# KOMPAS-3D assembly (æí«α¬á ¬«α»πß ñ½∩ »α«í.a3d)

Referenced files in D:\МОДЕЛЬ ТАНКА Т90\ПОДСБОРКИ\КОРПУС\: Сборка дно с пластиком.a3d, Сборка борт левый с пластиком.a3d, Сборка борт правый с пластиком.a3d, Сборка корпус лоб.a3d, Сборка корпус верх.a3d, Сборка корма.a3d, Сборка корма верх.a3d, Сборка крышка моторного.a3d, Сборка полка надгусеничная левая.a3d, Сборка полка надгусеничная правая.a3d
Referenced files in D:\МОДЕЛЬ ТАНКА Т90\ДЕТАЛИ\КОРПУС\МЕТАЛЛ\: перемычка корпуса.m3d, дно1скос.m3d, дно2 скос .m3d, тяга отвала.m3d, отвал.m3d
Referenced files in D:\МОДЕЛЬ ТАНКА Т90\ДЕТАЛИ\КОРПУС\МЕТАЛЛ\БАКИ\: Сборка бак левый 1.a3d, Сборка бак левый 2.a3d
